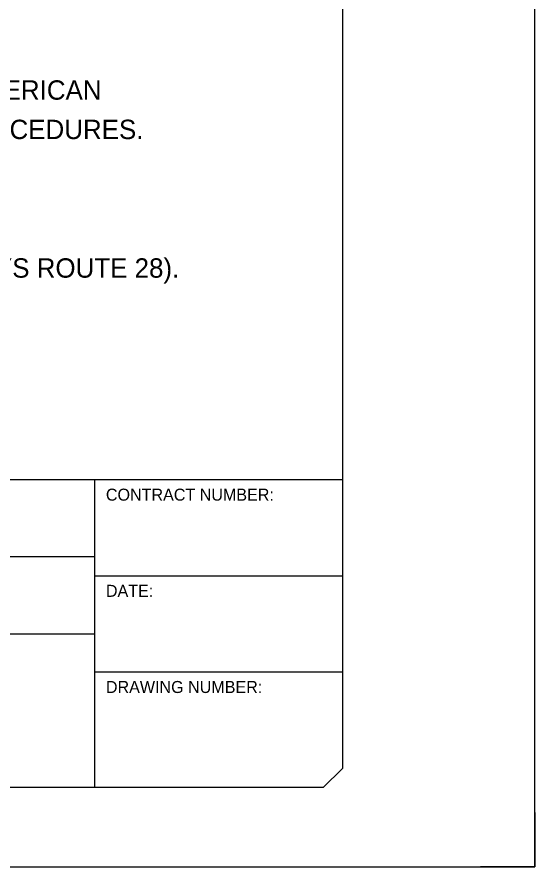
# Model space of a CAD drawing. Extents: x 359002 to 361405, y 1522603 to 1525369.
# Drawn here: x 361270.2 to 361404.8, y 1522602.9 to 1522823.9 of the extents above; entities that cross this region are included whole.
import ezdxf

# ---------------------------------------------------------------- set-up
doc = ezdxf.new("R2010")
doc.units = 0
for name, color, linetype in [('Manuscript', 7, 'Continuous'), ('SHEET_BORDER', 7, 'Continuous'), ('SHEET_BORDER_EDGE', 7, 'Continuous')]:
    doc.layers.add(name, color=color, linetype=linetype)

msp = doc.modelspace()

# ---------------------------------------------------------------- linework, layer by layer
at = {"layer": 'SHEET_BORDER'}
for p, q in [((361354.78, 1522703.52), (360683.16, 1522703.52)), ((361290.41, 1522623.52), (361290.41, 1522703.52)), ((361290.41, 1522683.52), (361146.66, 1522683.52)), ((361354.78, 1522678.52), (361290.41, 1522678.52)), ((360922.91, 1522663.52), (361290.41, 1522663.52)), ((361354.78, 1522653.52), (361290.41, 1522653.52))]:
    msp.add_line(p, q, dxfattribs=at)
msp.add_lwpolyline([(361354.78, 1522628.52), (361349.78, 1522623.52), (360099.78, 1522623.52), (360094.78, 1522628.52), (360094.78, 1523457.27), (360099.78, 1523462.27), (361349.78, 1523462.27), (361354.78, 1523457.27)], close=True, dxfattribs=at)
at = {"layer": 'SHEET_BORDER_EDGE'}
msp.add_lwpolyline([(360044.78, 1522602.9), (361404.78, 1522602.9), (361404.78, 1523482.89), (360044.78, 1523482.89)], close=True, dxfattribs=at)
msp.add_lwpolyline([(361404.78, 1522617.04), (361404.78, 1522602.9), (361390.64, 1522602.9)], dxfattribs=at)

# ---------------------------------------------------------------- texts
at = {"layer": 'Manuscript'}
for s, p in [('THE VERTICAL DATUM SHOWN HEREON IS REFERENCED TO THE NORTH AMERICAN', (361013.41, 1522802.37)), ('VERTICAL DATUM OF 1988 (GEOID 12A) IN US SURVEY FEET, USING GPS PROCEDURES.', (361013.41, 1522792.13)), ('CONTROL NETWORK FROM SOUTH TO NORTH ALONG MOHAWK STREET, (NYS ROUTE 28).', (361013.41, 1522756.1))]:
    msp.add_text(s, height=5.0361, dxfattribs=at).set_placement(p)
at = {"layer": 'SHEET_BORDER'}
for s, p in [('CONTRACT NUMBER:', (361293.29, 1522698.13)), ('DATE:', (361293.29, 1522673.13)), ('DRAWING NUMBER:', (361293.29, 1522648.13))]:
    msp.add_text(s, height=3.125, rotation=360, dxfattribs=at).set_placement(p)

doc.saveas('drawing.dxf')
